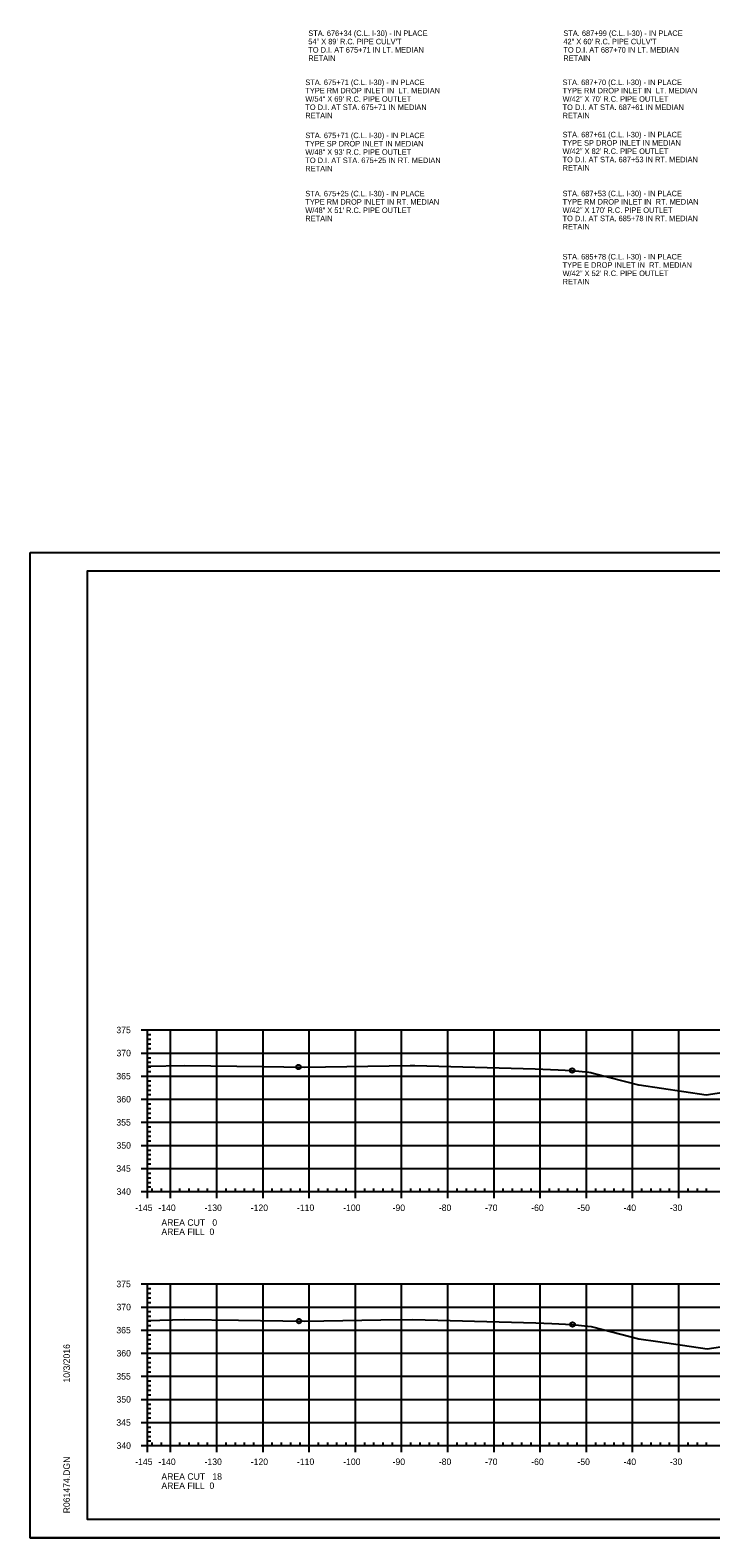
# Model space of a CAD drawing. Extents: x 1359801 to 1362404, y 372415 to 374228.
# Drawn here: x 1359800.9 to 1359948.3, y 373801.3 to 374127.8 of the extents above; entities that cross this region are included whole.
import ezdxf

# ---------------------------------------------------------------- set-up
doc = ezdxf.new("R2010")
doc.units = 0
for name, color, linetype in [('S_DRG_PT_SYM', 7, 'Continuous'), ('S_MAILBOX', 7, 'Continuous'), ('S_PRIMARY_CTL', 7, 'Continuous'), ('S_SHOULDER', 7, 'Continuous'), ('S_UTILITY_POLE_ANNOT', 7, 'Continuous'), ('S_UTL_PT_SYM', 7, 'Continuous'), ('S_WATER_UTILITIES', 7, 'Continuous')]:
    doc.layers.add(name, color=color, linetype=linetype)

msp = doc.modelspace()

# ---------------------------------------------------------------- linework, layer by layer
at = {"layer": 'S_DRG_PT_SYM'}
for points in [[(1359826.35, 373903.4), (1359834.34, 373903.58), (1359851.39, 373903.34), (1359860.33, 373903.23), (1359883.22, 373903.58), (1359883.67, 373903.58), (1359884.21, 373903.57), (1359910.28, 373902.86), (1359915.2, 373902.63), (1359918.25, 373902.5), (1359921.84, 373902.1), (1359922.28, 373902.05), (1359923.02, 373901.86), (1359932.6, 373899.42), (1359932.76, 373899.39), (1359947.25, 373897.21), (1359955.83, 373898.49)], [(1359826.35, 373848.38), (1359834.43, 373848.56), (1359846.04, 373848.4), (1359860.41, 373848.23), (1359876.85, 373848.47), (1359883.77, 373848.57), (1359891.85, 373848.35), (1359910.36, 373847.85), (1359913.86, 373847.69), (1359918.34, 373847.49), (1359920.89, 373847.21), (1359922.37, 373847.04), (1359924.92, 373846.4), (1359932.7, 373844.42), (1359936.8, 373843.79), (1359947.44, 373842.19), (1359953.74, 373843.13)]]:
    msp.add_lwpolyline(points, dxfattribs=at)
at = {"layer": 'S_MAILBOX'}
for p, q in [((1359826.35, 373911.27), (1360116.35, 373911.27)), ((1359826.35, 373876.27), (1359826.35, 373911.27)), ((1359831.35, 373876.27), (1359831.35, 373911.27)), ((1359841.35, 373876.27), (1359841.35, 373911.27)), ((1359851.35, 373876.27), (1359851.35, 373911.27)), ((1359861.35, 373876.27), (1359861.35, 373911.27)), ((1359871.35, 373876.27), (1359871.35, 373911.27)), ((1359881.35, 373876.27), (1359881.35, 373911.27)), ((1359891.35, 373876.27), (1359891.35, 373911.27)), ((1359901.35, 373876.27), (1359901.35, 373911.27)), ((1359911.35, 373876.27), (1359911.35, 373911.27)), ((1359921.35, 373876.27), (1359921.35, 373911.27)), ((1359931.35, 373876.27), (1359931.35, 373911.27)), ((1359941.35, 373876.27), (1359941.35, 373911.27)), ((1359826.35, 373906.27), (1360116.35, 373906.27)), ((1359826.35, 373901.27), (1360116.35, 373901.27)), ((1359826.35, 373896.27), (1360116.35, 373896.27)), ((1359826.35, 373891.27), (1360116.35, 373891.27)), ((1359826.35, 373886.27), (1360116.35, 373886.27)), ((1359826.35, 373881.27), (1360116.35, 373881.27)), ((1359826.35, 373876.27), (1360116.35, 373876.27)), ((1359826.35, 373856.27), (1360116.35, 373856.27)), ((1359826.35, 373821.27), (1359826.35, 373856.27)), ((1359831.35, 373821.27), (1359831.35, 373856.27)), ((1359841.35, 373821.27), (1359841.35, 373856.27)), ((1359851.35, 373821.27), (1359851.35, 373856.27)), ((1359861.35, 373821.27), (1359861.35, 373856.27)), ((1359871.35, 373821.27), (1359871.35, 373856.27)), ((1359881.35, 373821.27), (1359881.35, 373856.27)), ((1359891.35, 373821.27), (1359891.35, 373856.27)), ((1359901.35, 373821.27), (1359901.35, 373856.27)), ((1359911.35, 373821.27), (1359911.35, 373856.27)), ((1359921.35, 373821.27), (1359921.35, 373856.27)), ((1359931.35, 373821.27), (1359931.35, 373856.27)), ((1359941.35, 373821.27), (1359941.35, 373856.27)), ((1359826.35, 373851.27), (1360116.35, 373851.27)), ((1359826.35, 373846.27), (1360116.35, 373846.27)), ((1359826.35, 373841.27), (1360116.35, 373841.27)), ((1359826.35, 373836.27), (1360116.35, 373836.27)), ((1359826.35, 373831.27), (1360116.35, 373831.27)), ((1359826.35, 373826.27), (1360116.35, 373826.27)), ((1359826.35, 373821.27), (1360116.35, 373821.27))]:
    msp.add_line(p, q, dxfattribs=at)
at = {"layer": 'S_SHOULDER'}
for p, q in [((1359800.95, 374014.63), (1360134.28, 374014.63)), ((1359800.95, 373801.3), (1360134.28, 373801.3))]:
    msp.add_line(p, q, dxfattribs=at)
for points in [[(1359800.94, 374014.63), (1360134.28, 374014.63), (1360134.28, 373801.29), (1359800.94, 373801.29)], [(1360047.27, 374010.73), (1360047.27, 374000.85), (1360083, 374000.85), (1360083, 373997.93), (1360106.2, 373997.93), (1360106.2, 373973.6), (1360129.53, 373973.6), (1360129.53, 373805.27), (1359813.35, 373805.27), (1359813.35, 374010.73)]]:
    msp.add_lwpolyline(points, close=True, dxfattribs=at)
for centre in [(1359859.03, 373903.25), (1359918.25, 373902.5), (1359859.13, 373848.24), (1359918.34, 373847.49)]:
    msp.add_circle(centre, 0.5, dxfattribs=at)
at = {"layer": 'S_UTL_PT_SYM'}
for p, q in [((1359813.35, 374010.73), (1360129.53, 374010.73)), ((1359813.35, 373805.27), (1359813.35, 374010.73)), ((1359813.35, 373805.27), (1359813.35, 373805.27)), ((1360129.53, 373805.27), (1359813.35, 373805.27))]:
    msp.add_line(p, q, dxfattribs=at)
at = {"layer": 'S_WATER_UTILITIES'}
for p, q in [((1359824.95, 373911.27), (1359826.35, 373911.27)), ((1359826.35, 373876.27), (1359826.35, 373911.27)), ((1359826.35, 373910.27), (1359827.05, 373910.27)), ((1359826.35, 373909.27), (1359827.05, 373909.27)), ((1359826.35, 373908.27), (1359827.05, 373908.27)), ((1359824.95, 373906.27), (1359826.35, 373906.27)), ((1359826.35, 373907.27), (1359827.05, 373907.27)), ((1359826.35, 373905.27), (1359827.05, 373905.27)), ((1359824.95, 373901.27), (1359826.35, 373901.27)), ((1359826.35, 373904.27), (1359827.05, 373904.27)), ((1359826.35, 373903.27), (1359827.05, 373903.27)), ((1359826.35, 373902.27), (1359827.05, 373902.27)), ((1359826.35, 373900.27), (1359827.05, 373900.27)), ((1359826.35, 373899.27), (1359827.05, 373899.27)), ((1359826.35, 373898.27), (1359827.05, 373898.27)), ((1359824.95, 373896.27), (1359826.35, 373896.27)), ((1359826.35, 373897.27), (1359827.05, 373897.27)), ((1359826.35, 373895.27), (1359827.05, 373895.27)), ((1359826.35, 373894.27), (1359827.05, 373894.27)), ((1359826.35, 373893.27), (1359827.05, 373893.27)), ((1359826.35, 373892.27), (1359827.05, 373892.27)), ((1359824.95, 373891.27), (1359826.35, 373891.27)), ((1359826.35, 373890.27), (1359827.05, 373890.27)), ((1359826.35, 373889.27), (1359827.05, 373889.27)), ((1359826.35, 373888.27), (1359827.05, 373888.27)), ((1359824.95, 373886.27), (1359826.35, 373886.27)), ((1359826.35, 373887.27), (1359827.05, 373887.27)), ((1359826.35, 373885.27), (1359827.05, 373885.27)), ((1359826.35, 373884.27), (1359827.05, 373884.27)), ((1359826.35, 373883.27), (1359827.05, 373883.27)), ((1359826.35, 373882.27), (1359827.05, 373882.27)), ((1359824.95, 373881.27), (1359826.35, 373881.27)), ((1359826.35, 373880.27), (1359827.05, 373880.27)), ((1359826.35, 373879.27), (1359827.05, 373879.27)), ((1359826.35, 373878.27), (1359827.05, 373878.27)), ((1359824.95, 373876.27), (1359826.35, 373876.27)), ((1359826.35, 373877.27), (1359827.05, 373877.27)), ((1359826.35, 373876.27), (1359826.35, 373876.97)), ((1359826.35, 373876.27), (1360116.35, 373876.27)), ((1359826.35, 373874.87), (1359826.35, 373876.27)), ((1359827.35, 373876.27), (1359827.35, 373876.97)), ((1359829.35, 373876.27), (1359829.35, 373876.97)), ((1359831.35, 373874.87), (1359831.35, 373876.27)), ((1359833.35, 373876.27), (1359833.35, 373876.97)), ((1359835.35, 373876.27), (1359835.35, 373876.97)), ((1359837.35, 373876.27), (1359837.35, 373876.97)), ((1359839.35, 373876.27), (1359839.35, 373876.97)), ((1359841.35, 373874.87), (1359841.35, 373876.27)), ((1359843.35, 373876.27), (1359843.35, 373876.97)), ((1359845.35, 373876.27), (1359845.35, 373876.97)), ((1359847.35, 373876.27), (1359847.35, 373876.97)), ((1359849.35, 373876.27), (1359849.35, 373876.97)), ((1359851.35, 373874.87), (1359851.35, 373876.27)), ((1359853.35, 373876.27), (1359853.35, 373876.97)), ((1359855.35, 373876.27), (1359855.35, 373876.97)), ((1359857.35, 373876.27), (1359857.35, 373876.97)), ((1359859.35, 373876.27), (1359859.35, 373876.97)), ((1359861.35, 373874.87), (1359861.35, 373876.27)), ((1359863.35, 373876.27), (1359863.35, 373876.97)), ((1359865.35, 373876.27), (1359865.35, 373876.97)), ((1359867.35, 373876.27), (1359867.35, 373876.97)), ((1359869.35, 373876.27), (1359869.35, 373876.97)), ((1359871.35, 373874.87), (1359871.35, 373876.27)), ((1359873.35, 373876.27), (1359873.35, 373876.97)), ((1359875.35, 373876.27), (1359875.35, 373876.97)), ((1359877.35, 373876.27), (1359877.35, 373876.97)), ((1359879.35, 373876.27), (1359879.35, 373876.97)), ((1359881.35, 373874.87), (1359881.35, 373876.27)), ((1359883.35, 373876.27), (1359883.35, 373876.97)), ((1359885.35, 373876.27), (1359885.35, 373876.97)), ((1359887.35, 373876.27), (1359887.35, 373876.97)), ((1359889.35, 373876.27), (1359889.35, 373876.97)), ((1359891.35, 373874.87), (1359891.35, 373876.27)), ((1359893.35, 373876.27), (1359893.35, 373876.97)), ((1359895.35, 373876.27), (1359895.35, 373876.97)), ((1359897.35, 373876.27), (1359897.35, 373876.97)), ((1359899.35, 373876.27), (1359899.35, 373876.97)), ((1359901.35, 373874.87), (1359901.35, 373876.27)), ((1359903.35, 373876.27), (1359903.35, 373876.97)), ((1359905.35, 373876.27), (1359905.35, 373876.97)), ((1359907.35, 373876.27), (1359907.35, 373876.97)), ((1359909.35, 373876.27), (1359909.35, 373876.97)), ((1359911.35, 373874.87), (1359911.35, 373876.27)), ((1359913.35, 373876.27), (1359913.35, 373876.97)), ((1359915.35, 373876.27), (1359915.35, 373876.97)), ((1359917.35, 373876.27), (1359917.35, 373876.97)), ((1359919.35, 373876.27), (1359919.35, 373876.97)), ((1359921.35, 373874.87), (1359921.35, 373876.27)), ((1359923.35, 373876.27), (1359923.35, 373876.97)), ((1359925.35, 373876.27), (1359925.35, 373876.97)), ((1359927.35, 373876.27), (1359927.35, 373876.97)), ((1359929.35, 373876.27), (1359929.35, 373876.97)), ((1359931.35, 373874.87), (1359931.35, 373876.27)), ((1359933.35, 373876.27), (1359933.35, 373876.97)), ((1359935.35, 373876.27), (1359935.35, 373876.97)), ((1359937.35, 373876.27), (1359937.35, 373876.97)), ((1359939.35, 373876.27), (1359939.35, 373876.97)), ((1359941.35, 373874.87), (1359941.35, 373876.27)), ((1359943.35, 373876.27), (1359943.35, 373876.97)), ((1359945.35, 373876.27), (1359945.35, 373876.97)), ((1359947.35, 373876.27), (1359947.35, 373876.97)), ((1359824.95, 373856.27), (1359826.35, 373856.27)), ((1359826.35, 373821.27), (1359826.35, 373856.27)), ((1359826.35, 373855.27), (1359827.05, 373855.27)), ((1359826.35, 373854.27), (1359827.05, 373854.27)), ((1359826.35, 373853.27), (1359827.05, 373853.27)), ((1359826.35, 373852.27), (1359827.05, 373852.27)), ((1359824.95, 373851.27), (1359826.35, 373851.27)), ((1359826.35, 373850.27), (1359827.05, 373850.27)), ((1359826.35, 373849.27), (1359827.05, 373849.27)), ((1359824.95, 373846.27), (1359826.35, 373846.27)), ((1359826.35, 373848.27), (1359827.05, 373848.27)), ((1359826.35, 373847.27), (1359827.05, 373847.27)), ((1359826.35, 373845.27), (1359827.05, 373845.27)), ((1359826.35, 373844.27), (1359827.05, 373844.27)), ((1359826.35, 373843.27), (1359827.05, 373843.27)), ((1359824.95, 373841.27), (1359826.35, 373841.27)), ((1359826.35, 373842.27), (1359827.05, 373842.27)), ((1359826.35, 373840.27), (1359827.05, 373840.27)), ((1359826.35, 373839.27), (1359827.05, 373839.27)), ((1359824.95, 373836.27), (1359826.35, 373836.27)), ((1359826.35, 373838.27), (1359827.05, 373838.27)), ((1359826.35, 373837.27), (1359827.05, 373837.27)), ((1359826.35, 373835.27), (1359827.05, 373835.27)), ((1359826.35, 373834.27), (1359827.05, 373834.27)), ((1359826.35, 373833.27), (1359827.05, 373833.27)), ((1359824.95, 373831.27), (1359826.35, 373831.27)), ((1359826.35, 373832.27), (1359827.05, 373832.27)), ((1359826.35, 373830.27), (1359827.05, 373830.27)), ((1359826.35, 373829.27), (1359827.05, 373829.27)), ((1359824.95, 373826.27), (1359826.35, 373826.27)), ((1359826.35, 373828.27), (1359827.05, 373828.27)), ((1359826.35, 373827.27), (1359827.05, 373827.27)), ((1359826.35, 373825.27), (1359827.05, 373825.27)), ((1359826.35, 373824.27), (1359827.05, 373824.27)), ((1359826.35, 373823.27), (1359827.05, 373823.27)), ((1359824.95, 373821.27), (1359826.35, 373821.27)), ((1359826.35, 373822.27), (1359827.05, 373822.27)), ((1359826.35, 373821.27), (1359826.35, 373821.97)), ((1359826.35, 373821.27), (1360116.35, 373821.27)), ((1359826.35, 373819.87), (1359826.35, 373821.27)), ((1359827.35, 373821.27), (1359827.35, 373821.97)), ((1359829.35, 373821.27), (1359829.35, 373821.97)), ((1359831.35, 373819.87), (1359831.35, 373821.27)), ((1359833.35, 373821.27), (1359833.35, 373821.97)), ((1359835.35, 373821.27), (1359835.35, 373821.97)), ((1359837.35, 373821.27), (1359837.35, 373821.97)), ((1359839.35, 373821.27), (1359839.35, 373821.97)), ((1359841.35, 373819.87), (1359841.35, 373821.27)), ((1359843.35, 373821.27), (1359843.35, 373821.97)), ((1359845.35, 373821.27), (1359845.35, 373821.97)), ((1359847.35, 373821.27), (1359847.35, 373821.97)), ((1359849.35, 373821.27), (1359849.35, 373821.97)), ((1359851.35, 373819.87), (1359851.35, 373821.27)), ((1359853.35, 373821.27), (1359853.35, 373821.97)), ((1359855.35, 373821.27), (1359855.35, 373821.97)), ((1359857.35, 373821.27), (1359857.35, 373821.97)), ((1359859.35, 373821.27), (1359859.35, 373821.97)), ((1359861.35, 373819.87), (1359861.35, 373821.27)), ((1359863.35, 373821.27), (1359863.35, 373821.97)), ((1359865.35, 373821.27), (1359865.35, 373821.97)), ((1359867.35, 373821.27), (1359867.35, 373821.97)), ((1359869.35, 373821.27), (1359869.35, 373821.97)), ((1359871.35, 373819.87), (1359871.35, 373821.27)), ((1359873.35, 373821.27), (1359873.35, 373821.97)), ((1359875.35, 373821.27), (1359875.35, 373821.97)), ((1359877.35, 373821.27), (1359877.35, 373821.97)), ((1359879.35, 373821.27), (1359879.35, 373821.97)), ((1359881.35, 373819.87), (1359881.35, 373821.27)), ((1359883.35, 373821.27), (1359883.35, 373821.97)), ((1359885.35, 373821.27), (1359885.35, 373821.97)), ((1359887.35, 373821.27), (1359887.35, 373821.97)), ((1359889.35, 373821.27), (1359889.35, 373821.97)), ((1359891.35, 373819.87), (1359891.35, 373821.27)), ((1359893.35, 373821.27), (1359893.35, 373821.97)), ((1359895.35, 373821.27), (1359895.35, 373821.97)), ((1359897.35, 373821.27), (1359897.35, 373821.97)), ((1359899.35, 373821.27), (1359899.35, 373821.97)), ((1359901.35, 373819.87), (1359901.35, 373821.27)), ((1359903.35, 373821.27), (1359903.35, 373821.97)), ((1359905.35, 373821.27), (1359905.35, 373821.97)), ((1359907.35, 373821.27), (1359907.35, 373821.97)), ((1359909.35, 373821.27), (1359909.35, 373821.97)), ((1359911.35, 373819.87), (1359911.35, 373821.27)), ((1359913.35, 373821.27), (1359913.35, 373821.97)), ((1359915.35, 373821.27), (1359915.35, 373821.97)), ((1359917.35, 373821.27), (1359917.35, 373821.97)), ((1359919.35, 373821.27), (1359919.35, 373821.97)), ((1359921.35, 373819.87), (1359921.35, 373821.27)), ((1359923.35, 373821.27), (1359923.35, 373821.97)), ((1359925.35, 373821.27), (1359925.35, 373821.97)), ((1359927.35, 373821.27), (1359927.35, 373821.97)), ((1359929.35, 373821.27), (1359929.35, 373821.97)), ((1359931.35, 373819.87), (1359931.35, 373821.27)), ((1359933.35, 373821.27), (1359933.35, 373821.97)), ((1359935.35, 373821.27), (1359935.35, 373821.97)), ((1359937.35, 373821.27), (1359937.35, 373821.97)), ((1359939.35, 373821.27), (1359939.35, 373821.97)), ((1359941.35, 373819.87), (1359941.35, 373821.27)), ((1359943.35, 373821.27), (1359943.35, 373821.97)), ((1359945.35, 373821.27), (1359945.35, 373821.97)), ((1359947.35, 373821.27), (1359947.35, 373821.97))]:
    msp.add_line(p, q, dxfattribs=at)

# ---------------------------------------------------------------- texts
at = {"layer": 'S_PRIMARY_CTL'}
for s, p in [('375', (1359819.6, 373910.57)), ('370', (1359819.63, 373905.57)), ('365', (1359819.6, 373900.57)), ('360', (1359819.63, 373895.57)), ('355', (1359819.6, 373890.57)), ('350', (1359819.63, 373885.57)), ('345', (1359819.6, 373880.57)), ('340', (1359819.63, 373875.57)), ('-145', (1359823.68, 373872.07)), ('-140', (1359828.69, 373872.07)), ('-130', (1359838.69, 373872.07)), ('-120', (1359848.69, 373872.07)), ('-110', (1359858.69, 373872.07)), ('-100', (1359868.69, 373872.07)), ('-90', (1359879.39, 373872.07)), ('-80', (1359889.39, 373872.07)), ('-70', (1359899.39, 373872.07)), ('-60', (1359909.39, 373872.07)), ('-50', (1359919.39, 373872.07)), ('-40', (1359929.39, 373872.07)), ('-30', (1359939.39, 373872.07)), ('AREA CUT   0', (1359829.35, 373868.87)), ('AREA FILL  0', (1359829.35, 373866.87)), ('375', (1359819.6, 373855.57)), ('370', (1359819.63, 373850.57)), ('365', (1359819.6, 373845.57)), ('360', (1359819.63, 373840.57)), ('355', (1359819.6, 373835.57)), ('350', (1359819.63, 373830.57)), ('345', (1359819.6, 373825.57)), ('340', (1359819.63, 373820.57)), ('-145', (1359823.68, 373817.07)), ('-140', (1359828.69, 373817.07)), ('-130', (1359838.69, 373817.07)), ('-120', (1359848.69, 373817.07)), ('-110', (1359858.69, 373817.07)), ('-100', (1359868.69, 373817.07)), ('-90', (1359879.39, 373817.07)), ('-80', (1359889.39, 373817.07)), ('-70', (1359899.39, 373817.07)), ('-60', (1359909.39, 373817.07)), ('-50', (1359919.39, 373817.07)), ('-40', (1359929.39, 373817.07)), ('-30', (1359939.39, 373817.07)), ('AREA CUT   18', (1359829.35, 373813.87)), ('AREA FILL  0', (1359829.35, 373811.87))]:
    msp.add_text(s, height=1.4, dxfattribs=at).set_placement(p)
at = {"layer": 'S_SHOULDER'}
for p in [(1359910.23, 373902.81), (1359910.32, 373847.8)]:
    msp.add_text('+', height=0.1, dxfattribs=at).set_placement(p)
at = {"layer": 'S_UTILITY_POLE_ANNOT'}
for s, p in [('STA. 676+34 (C.L. I-30) - IN PLACE', (1359861.14, 374126.51)), ('STA. 687+99 (C.L. I-30) - IN PLACE', (1359916.35, 374126.51)), ('TO D.I. AT 675+71 IN LT. MEDIAN', (1359861.14, 374122.91)), ('54" X 89\' R.C. PIPE CULV\'T', (1359861.14, 374124.71)), ('42" X 60\' R.C. PIPE CULV\'T', (1359916.35, 374124.71)), ('TO D.I. AT 687+70 IN LT. MEDIAN', (1359916.35, 374122.91)), ('RETAIN ', (1359861.14, 374121.11)), ('RETAIN ', (1359916.35, 374121.11)), ('STA. 675+71 (C.L. I-30) - IN PLACE', (1359860.5, 374115.88)), ('STA. 687+70 (C.L. I-30) - IN PLACE', (1359916.18, 374115.88)), ('W/54" X 69\' R.C. PIPE OUTLET', (1359860.5, 374112.28)), ('TYPE RM DROP INLET IN  LT. MEDIAN', (1359860.5, 374114.08)), ('W/42" X 70\' R.C. PIPE OUTLET', (1359916.18, 374112.28)), ('TYPE RM DROP INLET IN  LT. MEDIAN', (1359916.18, 374114.08)), ('TO D.I. AT STA. 675+71 IN MEDIAN', (1359860.5, 374110.48)), ('TO D.I. AT STA. 687+61 IN MEDIAN', (1359916.18, 374110.48)), ('RETAIN', (1359860.5, 374108.68)), ('RETAIN', (1359916.18, 374108.68)), ('TYPE SP DROP INLET IN MEDIAN', (1359860.5, 374102.59)), ('STA. 675+71 (C.L. I-30) - IN PLACE', (1359860.5, 374104.39)), ('TYPE SP DROP INLET IN MEDIAN', (1359916.18, 374102.76)), ('STA. 687+61 (C.L. I-30) - IN PLACE', (1359916.18, 374104.56)), ('W/48" X 93\' R.C. PIPE OUTLET ', (1359860.5, 374100.79)), ('W/42" X 82\' R.C. PIPE OUTLET', (1359916.18, 374100.96)), ('TO D.I. AT STA. 687+53 IN RT. MEDIAN', (1359916.18, 374099.16)), ('TO D.I. AT STA. 675+25 IN RT. MEDIAN', (1359860.5, 374098.99)), ('RETAIN', (1359860.5, 374097.19)), ('RETAIN', (1359916.18, 374097.36)), ('TYPE RM DROP INLET IN RT. MEDIAN', (1359860.5, 374089.98)), ('STA. 675+25 (C.L. I-30) - IN PLACE', (1359860.5, 374091.78)), ('TYPE RM DROP INLET IN  RT. MEDIAN', (1359916.18, 374090.01)), ('STA. 687+53 (C.L. I-30) - IN PLACE', (1359916.18, 374091.81)), ('W/48" X 51\' R.C. PIPE OUTLET', (1359860.5, 374088.18)), ('RETAIN', (1359860.5, 374086.38)), ('W/42" X 170\' R.C. PIPE OUTLET', (1359916.18, 374088.21)), ('TO D.I. AT STA. 685+78 IN RT. MEDIAN', (1359916.18, 374086.41)), ('RETAIN', (1359916.18, 374084.61)), ('TYPE E DROP INLET IN  RT. MEDIAN', (1359916.18, 374076.32)), ('STA. 685+78 (C.L. I-30) - IN PLACE', (1359916.18, 374078.12)), ('W/42" X 52\' R.C. PIPE OUTLET', (1359916.18, 374074.52)), ('RETAIN', (1359916.18, 374072.72))]:
    msp.add_text(s, height=1.2, dxfattribs=at).set_placement(p)
at = {"layer": 'S_UTL_PT_SYM'}
for s, p in [('10/3/2016', (1359809.54, 373834.92)), ('R061474.DGN', (1359809.54, 373806.6))]:
    msp.add_text(s, height=1.4, rotation=90, dxfattribs=at).set_placement(p)

doc.saveas('drawing.dxf')
